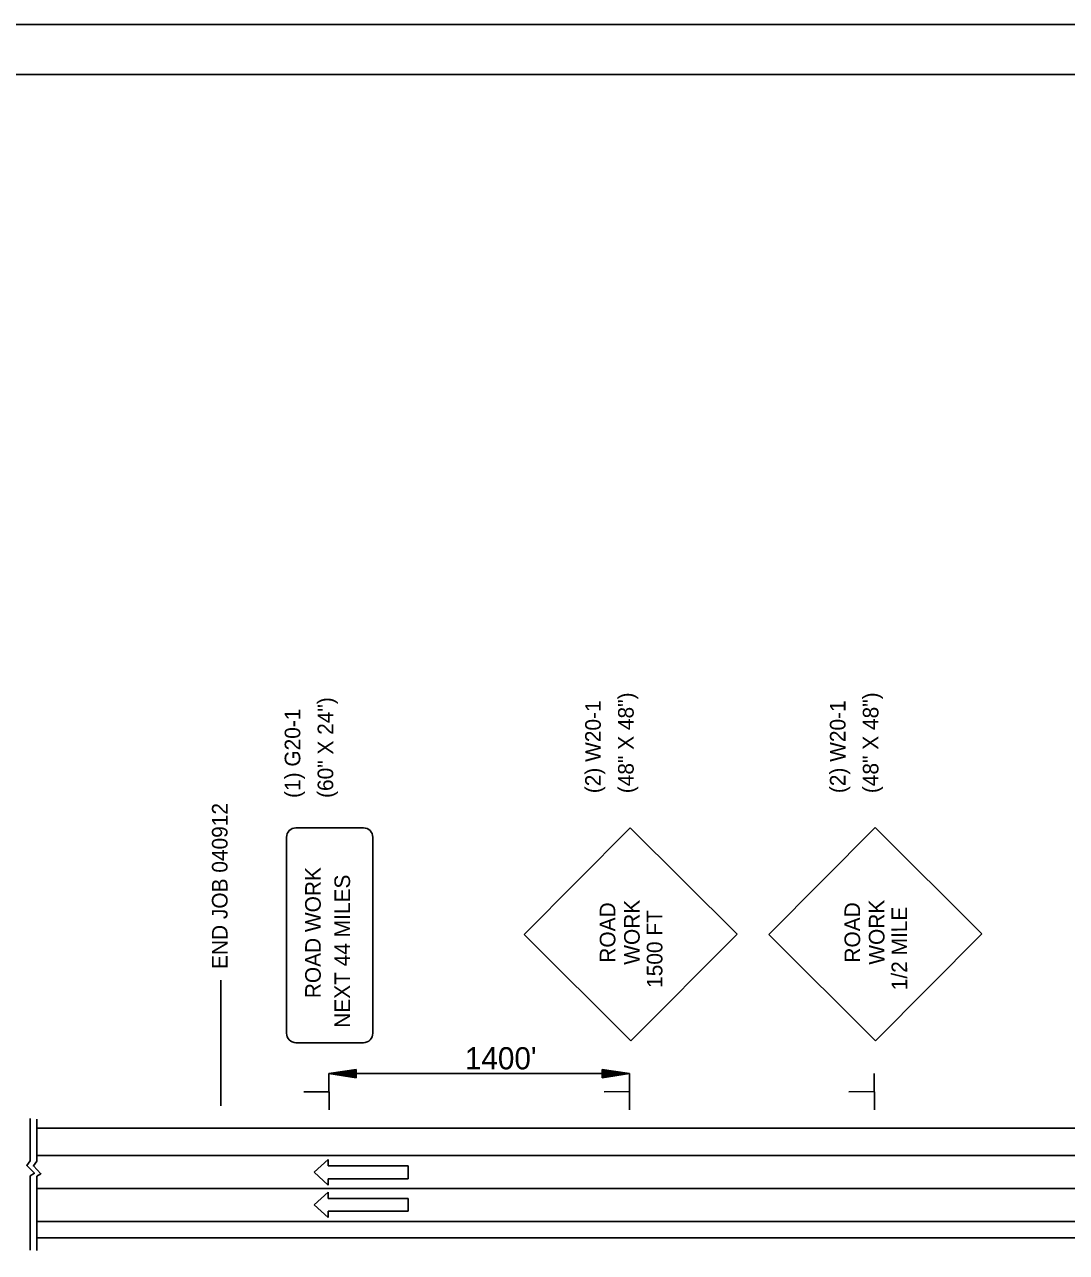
# Model space of a CAD drawing. Extents: x 13744624 to 13747958, y 3814079 to 3815145.
# Drawn here: x 13745457.8 to 13745864.8, y 3814665.8 to 3815145.4 of the extents above; entities that cross this region are included whole.
import ezdxf

# ---------------------------------------------------------------- set-up
doc = ezdxf.new("R2010")
doc.units = 0
for name, color, linetype in [('Default', 7, 'Continuous'), ('R_Border', 7, 'Continuous'), ('R_Draft', 7, 'Continuous'), ('R_MOT', 7, 'Continuous'), ('R_No Plot', 7, 'Continuous')]:
    doc.layers.add(name, color=color, linetype=linetype)

msp = doc.modelspace()

# ---------------------------------------------------------------- linework, layer by layer
at = {"layer": 'Default'}
for p, q in [((13745534.42, 3814722.97), (13745534.42, 3814772.08)), ((13745694.11, 3814735.63), (13745576.69, 3814735.61)), ((13745459.98, 3814718.02), (13745459.98, 3814701.58)), ((13745462.55, 3814717.83), (13745462.55, 3814701.4)), ((13746056.77, 3814714.29), (13745462.99, 3814714.29)), ((13746056.77, 3814703.57), (13745462.99, 3814703.57)), ((13745459.98, 3814695.71), (13745459.98, 3814666.68)), ((13745462.55, 3814695.52), (13745462.55, 3814666.5)), ((13746056.77, 3814690.71), (13745462.99, 3814690.71)), ((13746056.77, 3814677.86), (13745462.99, 3814677.86)), ((13746056.77, 3814671.43), (13745462.99, 3814671.43))]:
    msp.add_line(p, q, dxfattribs=at)
for points in [[(13745459.98, 3814695.71), (13745461.63, 3814696.69), (13745458.68, 3814699.73), (13745459.98, 3814701.58)], [(13745462.55, 3814695.52), (13745464.21, 3814696.51), (13745461.26, 3814699.55), (13745462.55, 3814701.4)]]:
    msp.add_lwpolyline(points, dxfattribs=at)
at = {"layer": 'R_Border'}
msp.add_line((13744686.23, 3815125.92), (13746267.13, 3815125.92), dxfattribs=at)
at = {"layer": 'R_Draft'}
for p, q in [((13745587.4, 3814737.21), (13745576.69, 3814735.61)), ((13745587.4, 3814734), (13745576.69, 3814735.61)), ((13745587.4, 3814736.95), (13745578.48, 3814735.61)), ((13745587.4, 3814734.27), (13745578.48, 3814735.61)), ((13745587.4, 3814736.67), (13745580.32, 3814735.61)), ((13745587.4, 3814734.54), (13745580.32, 3814735.61)), ((13745587.4, 3814736.4), (13745582.11, 3814735.61)), ((13745587.4, 3814734.81), (13745582.11, 3814735.61)), ((13745587.4, 3814736.13), (13745583.92, 3814735.61)), ((13745587.4, 3814735.09), (13745583.92, 3814735.61)), ((13745587.4, 3814735.86), (13745585.71, 3814735.61)), ((13745587.4, 3814735.35), (13745585.71, 3814735.61)), ((13745587.4, 3814734), (13745587.4, 3814737.21)), ((13745683.4, 3814737.24), (13745694.11, 3814735.63)), ((13745683.4, 3814737.24), (13745683.4, 3814734.02)), ((13745683.4, 3814736.97), (13745692.33, 3814735.63)), ((13745683.4, 3814736.7), (13745690.48, 3814735.63)), ((13745683.4, 3814736.43), (13745688.7, 3814735.63)), ((13745683.4, 3814736.15), (13745686.88, 3814735.63)), ((13745683.4, 3814735.88), (13745685.09, 3814735.63)), ((13745683.4, 3814734.02), (13745694.11, 3814735.63)), ((13745683.4, 3814735.11), (13745686.88, 3814735.63)), ((13745683.4, 3814734.56), (13745690.48, 3814735.63)), ((13745683.4, 3814734.29), (13745692.33, 3814735.63)), ((13745683.4, 3814734.83), (13745688.7, 3814735.63)), ((13745683.4, 3814735.38), (13745685.09, 3814735.63))]:
    msp.add_line(p, q, dxfattribs=at)
at = {"layer": 'R_MOT'}
for p, q in [((13745590.17, 3814831.61), (13745563.82, 3814831.61)), ((13745694.45, 3814831.67), (13745652.94, 3814789.98)), ((13745694.45, 3814831.67), (13745736.14, 3814790.13)), ((13745790.07, 3814831.7), (13745748.56, 3814790.01)), ((13745790.07, 3814831.7), (13745831.76, 3814790.15)), ((13745560.13, 3814827.92), (13745560.13, 3814751.37)), ((13745593.86, 3814827.92), (13745593.86, 3814751.37)), ((13745652.94, 3814789.98), (13745694.6, 3814748.44)), ((13745736.14, 3814790.13), (13745694.6, 3814748.44)), ((13745748.56, 3814790.01), (13745790.21, 3814748.46)), ((13745831.76, 3814790.15), (13745790.21, 3814748.46)), ((13745590.17, 3814747.68), (13745563.82, 3814747.68)), ((13745576.69, 3814735.61), (13745576.75, 3814721.42)), ((13745694.11, 3814735.63), (13745694.18, 3814721.45)), ((13745789.73, 3814735.66), (13745789.79, 3814721.48)), ((13745694.15, 3814728.57), (13745684.26, 3814728.53)), ((13745789.76, 3814728.6), (13745779.87, 3814728.56)), ((13745576.72, 3814728.55), (13745566.84, 3814728.51)), ((13745576.43, 3814702.06), (13745570.96, 3814697.07)), ((13745576.43, 3814699.56), (13745576.43, 3814702.06)), ((13745570.96, 3814697.07), (13745576.43, 3814692.08)), ((13745607.6, 3814699.56), (13745576.43, 3814699.56)), ((13745607.6, 3814694.57), (13745607.6, 3814699.56)), ((13745576.43, 3814692.08), (13745576.43, 3814694.57)), ((13745576.43, 3814694.57), (13745607.6, 3814694.57)), ((13745570.96, 3814684.36), (13745576.43, 3814689.35)), ((13745576.43, 3814689.35), (13745576.43, 3814686.86)), ((13745576.43, 3814686.86), (13745607.6, 3814686.86)), ((13745607.6, 3814686.86), (13745607.6, 3814681.87)), ((13745576.43, 3814679.37), (13745570.96, 3814684.36)), ((13745607.6, 3814681.87), (13745576.43, 3814681.87)), ((13745576.43, 3814681.87), (13745576.43, 3814679.37))]:
    msp.add_line(p, q, dxfattribs=at)
for centre, start, end in [((13745563.82, 3814827.92), 90, 180), ((13745590.17, 3814827.92), 0, 90), ((13745563.82, 3814751.37), 180, 270), ((13745590.17, 3814751.37), 270, 0)]:
    msp.add_arc(centre, 3.69, start, end, dxfattribs=at)
at = {"layer": 'R_No Plot'}
msp.add_line((13744624.22, 3815145.39), (13746290.89, 3815145.39), dxfattribs=at)
for points in [[(13744624.19, 3815145.39), (13746290.89, 3815145.39), (13746290.89, 3814078.71), (13744624.19, 3814078.71)], [(13745855.83, 3815125.92), (13745953.93, 3815125.92), (13745953.93, 3815076.52), (13746034.49, 3815076.52), (13746150.48, 3815076.52), (13746150.48, 3814954.86), (13746267.13, 3814954.86), (13746267.13, 3814098.62), (13744686.23, 3814098.62), (13744686.23, 3815125.92)]]:
    msp.add_lwpolyline(points, close=True, dxfattribs=at)

# ---------------------------------------------------------------- texts
at = {"layer": 'Default'}
msp.add_text('END JOB 040912', height=6.1, rotation=90, dxfattribs=at).set_placement((13745537.1, 3814776.48))
msp.add_text("1400'", height=8.664, dxfattribs=at).set_placement((13745629.83, 3814737.28))
at = {"layer": 'R_MOT'}
for s, rotation, p in [('(60" X 24")', 90, (13745578.38, 3814843.29)), ('(48" X 48")', 90, (13745695.76, 3814845.14)), ('(48" X 48")', 90, (13745791.38, 3814845.17)), ('(1) G20-1', 90, (13745565.52, 3814843.29)), ('(2) W20-1', 90, (13745682.91, 3814845.14)), ('(2) W20-1', 90, (13745778.52, 3814845.17)), ('ROAD WORK', 90, (13745573.51, 3814765.07)), (' NEXT 44 MILES', 90, (13745584.96, 3814751.24)), ('ROAD', 90.1004, (13745688.62, 3814778.94)), ('WORK', 90.1003, (13745698.13, 3814778.15)), ('ROAD', 90.1004, (13745784.24, 3814778.97)), ('WORK', 90.1003, (13745793.75, 3814778.17)), (' 1500 FT', 90.0995, (13745707.01, 3814766.83)), (' 1/2 MILE', 90.0995, (13745802.62, 3814765.92))]:
    msp.add_text(s, height=6.1, rotation=rotation, dxfattribs=at).set_placement(p)

doc.saveas('drawing.dxf')
